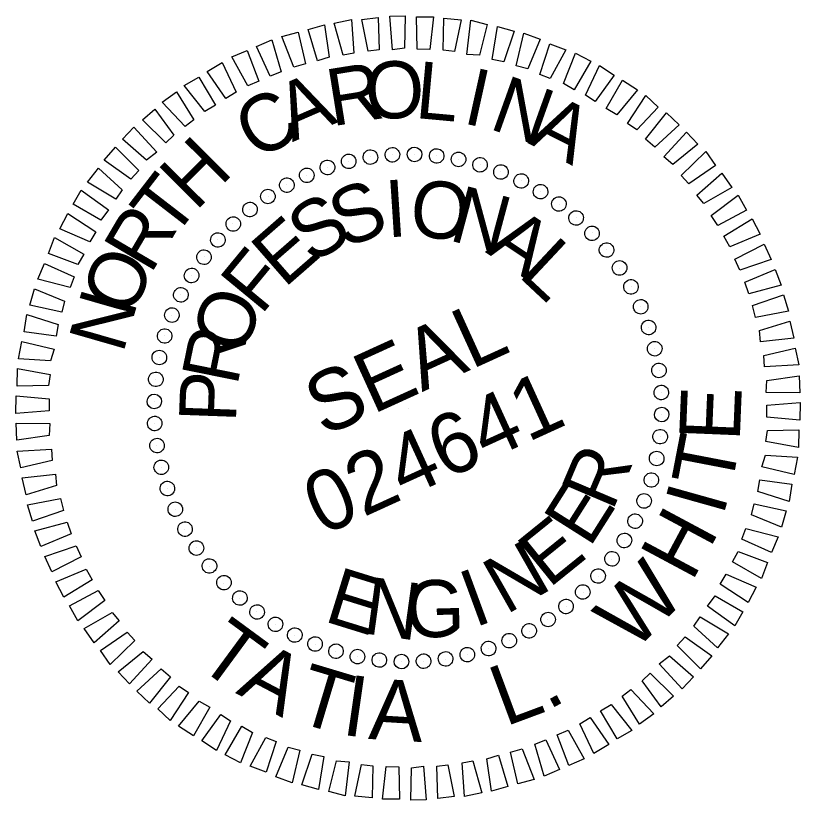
# Model space of a CAD drawing. Extents: x 2245059 to 2247045, y 661437 to 663204.
# Drawn here: x 2246812.7 to 2246890.2, y 663085.4 to 663163 of the extents above; entities that cross this region are included whole.
import ezdxf

# ---------------------------------------------------------------- set-up
doc = ezdxf.new("R2010")
doc.units = 0
doc.layers.add('Sheet Professional Seal CELL', color=7, linetype='Continuous')

msp = doc.modelspace()

# ---------------------------------------------------------------- linework, layer by layer
at = {"layer": 'Sheet Professional Seal CELL'}
for p, q in [((2246849.929, 663149.276), (2246849.929, 663149.276)), ((2246852.123, 663149.287), (2246852.123, 663149.287)), ((2246854.312, 663149.186), (2246854.312, 663149.186)), ((2246845.631, 663148.58), (2246845.631, 663148.58)), ((2246847.728, 663149.042), (2246847.728, 663149.042)), ((2246856.468, 663148.795), (2246856.468, 663148.795)), ((2246843.529, 663148.006), (2246843.529, 663148.006)), ((2246858.621, 663148.293), (2246858.621, 663148.293)), ((2246841.465, 663147.23), (2246841.465, 663147.23)), ((2246860.653, 663147.571), (2246860.653, 663147.571)), ((2246839.485, 663146.272), (2246839.485, 663146.272)), ((2246862.703, 663146.692), (2246862.703, 663146.692)), ((2246864.566, 663145.619), (2246864.566, 663145.619)), ((2246837.653, 663145.107), (2246837.653, 663145.107)), ((2246835.817, 663143.83), (2246835.817, 663143.83)), ((2246866.401, 663144.367), (2246866.401, 663144.367)), ((2246868.119, 663143.008), (2246868.119, 663143.008)), ((2246834.155, 663142.413), (2246834.155, 663142.413)), ((2246869.677, 663141.52), (2246869.677, 663141.52)), ((2246832.667, 663140.855), (2246832.667, 663140.855)), ((2246871.094, 663139.858), (2246871.094, 663139.858)), ((2246831.308, 663139.136), (2246831.308, 663139.136)), ((2246872.371, 663138.022), (2246872.371, 663138.022)), ((2246830.056, 663137.302), (2246830.056, 663137.302)), ((2246873.536, 663136.191), (2246873.536, 663136.191)), ((2246828.983, 663135.438), (2246828.983, 663135.438)), ((2246874.494, 663134.21), (2246874.494, 663134.21)), ((2246828.104, 663133.389), (2246828.104, 663133.389)), ((2246875.271, 663132.146), (2246875.271, 663132.146)), ((2246827.382, 663131.356), (2246827.382, 663131.356)), ((2246875.844, 663130.044), (2246875.844, 663130.044)), ((2246826.88, 663129.204), (2246826.88, 663129.204)), ((2246876.306, 663127.947), (2246876.306, 663127.947)), ((2246826.489, 663127.047), (2246826.489, 663127.047)), ((2246876.54, 663125.746), (2246876.54, 663125.746)), ((2246826.388, 663124.858), (2246826.388, 663124.858)), ((2246851.47, 663124.205), (2246851.47, 663124.205)), ((2246876.551, 663123.553), (2246876.551, 663123.553)), ((2246826.399, 663122.665), (2246826.399, 663122.665)), ((2246876.45, 663121.363), (2246876.45, 663121.363)), ((2246826.634, 663120.464), (2246826.634, 663120.464)), ((2246876.06, 663119.207), (2246876.06, 663119.207)), ((2246827.095, 663118.367), (2246827.095, 663118.367)), ((2246875.557, 663117.055), (2246875.557, 663117.055)), ((2246827.669, 663116.265), (2246827.669, 663116.265)), ((2246874.836, 663115.022), (2246874.836, 663115.022)), ((2246828.445, 663114.201), (2246828.445, 663114.201)), ((2246873.957, 663112.973), (2246873.957, 663112.973)), ((2246829.403, 663112.22), (2246829.403, 663112.22)), ((2246830.568, 663110.388), (2246830.568, 663110.388)), ((2246872.883, 663111.109), (2246872.883, 663111.109)), ((2246871.631, 663109.275), (2246871.631, 663109.275)), ((2246831.845, 663108.553), (2246831.845, 663108.553)), ((2246870.272, 663107.556), (2246870.272, 663107.556)), ((2246833.262, 663106.891), (2246833.262, 663106.891)), ((2246868.784, 663105.998), (2246868.784, 663105.998)), ((2246834.82, 663105.403), (2246834.82, 663105.403)), ((2246867.122, 663104.581), (2246867.122, 663104.581)), ((2246836.539, 663104.044), (2246836.539, 663104.044)), ((2246838.374, 663102.792), (2246838.374, 663102.792)), ((2246865.287, 663103.304), (2246865.287, 663103.304)), ((2246863.455, 663102.139), (2246863.455, 663102.139)), ((2246840.237, 663101.718), (2246840.237, 663101.718)), ((2246861.474, 663101.181), (2246861.474, 663101.181)), ((2246842.286, 663100.839), (2246842.286, 663100.839)), ((2246859.41, 663100.405), (2246859.41, 663100.405)), ((2246844.319, 663100.118), (2246844.319, 663100.118)), ((2246846.471, 663099.615), (2246846.471, 663099.615)), ((2246857.309, 663099.831), (2246857.309, 663099.831)), ((2246848.628, 663099.225), (2246848.628, 663099.225)), ((2246850.817, 663099.124), (2246850.817, 663099.124)), ((2246853.01, 663099.135), (2246853.01, 663099.135)), ((2246855.211, 663099.369), (2246855.211, 663099.369))]:
    msp.add_line(p, q, dxfattribs=at)
for points in [[(2246845.068, 663159.094), (2246844.175, 663162.258), (2246845.887, 663162.6), (2246846.127, 663159.302)], [(2246847.521, 663159.498), (2246846.918, 663162.63), (2246848.535, 663162.818), (2246848.622, 663159.615)], [(2246849.942, 663159.613), (2246849.681, 663162.956), (2246851.204, 663162.991), (2246851.134, 663159.771)], [(2246852.383, 663159.682), (2246852.297, 663162.885), (2246853.997, 663162.891), (2246853.612, 663159.638)], [(2246854.953, 663159.59), (2246854.999, 663162.743), (2246856.717, 663162.592), (2246856.066, 663159.438)], [(2246857.288, 663159.17), (2246857.677, 663162.535), (2246859.295, 663162.119), (2246858.537, 663159.081)], [(2246842.52, 663158.536), (2246841.601, 663161.635), (2246843.206, 663162.092), (2246843.674, 663158.898)], [(2246859.775, 663158.656), (2246860.317, 663161.926), (2246861.957, 663161.464), (2246860.93, 663158.413)], [(2246840.17, 663157.904), (2246839.004, 663160.945), (2246840.629, 663161.356), (2246841.345, 663158.22)], [(2246862.147, 663158.034), (2246862.933, 663161.25), (2246864.523, 663160.656), (2246863.322, 663157.746)], [(2246837.833, 663157.004), (2246836.485, 663159.961), (2246838.007, 663160.6), (2246838.946, 663157.456)], [(2246864.511, 663157.189), (2246865.492, 663160.219), (2246867.082, 663159.625), (2246865.525, 663156.772)], [(2246835.629, 663156.054), (2246834.053, 663158.907), (2246835.575, 663159.546), (2246836.741, 663156.506)], [(2246866.85, 663156.277), (2246868.009, 663159.278), (2246869.524, 663158.486), (2246867.902, 663155.657)], [(2246833.458, 663154.789), (2246831.63, 663157.472), (2246833.093, 663158.36), (2246834.487, 663155.423)], [(2246869.024, 663155.125), (2246870.382, 663158.052), (2246871.848, 663157.127), (2246869.964, 663154.51)], [(2246831.398, 663153.52), (2246829.343, 663156.1), (2246830.782, 663156.921), (2246832.428, 663154.154)], [(2246871.057, 663153.799), (2246872.68, 663156.627), (2246874.167, 663155.657), (2246872.109, 663153.18)], [(2246829.443, 663152.024), (2246827.181, 663154.454), (2246828.582, 663155.478), (2246830.295, 663152.687)], [(2246873.153, 663152.337), (2246874.974, 663155.091), (2246876.209, 663153.95), (2246874.093, 663151.721)], [(2246827.529, 663150.437), (2246825.238, 663152.689), (2246826.461, 663153.742), (2246828.339, 663151.191)], [(2246874.954, 663150.795), (2246877.016, 663153.384), (2246878.272, 663152.198), (2246875.866, 663150.002)], [(2246825.632, 663148.692), (2246823.246, 663150.792), (2246824.362, 663151.96), (2246826.645, 663149.484)], [(2246876.748, 663149.031), (2246878.984, 663151.479), (2246880.128, 663150.297), (2246877.639, 663148.283)], [(2246824.066, 663146.824), (2246821.448, 663148.708), (2246822.568, 663149.988), (2246824.88, 663147.69)], [(2246878.472, 663147.179), (2246880.906, 663149.553), (2246881.864, 663148.176), (2246879.226, 663146.369)], [(2246822.607, 663144.84), (2246819.804, 663146.53), (2246820.882, 663147.901), (2246823.223, 663145.781)], [(2246880.014, 663145.244), (2246882.486, 663147.415), (2246883.464, 663145.993), (2246880.722, 663144.413)], [(2246821.124, 663142.79), (2246818.383, 663144.343), (2246819.172, 663145.747), (2246821.876, 663143.793)], [(2246881.419, 663143.247), (2246884.085, 663145.232), (2246884.927, 663143.748), (2246882.099, 663142.238)], [(2246820.018, 663140.637), (2246817.066, 663141.929), (2246817.858, 663143.444), (2246820.612, 663141.623)], [(2246882.687, 663141.188), (2246885.479, 663142.9), (2246886.275, 663141.395), (2246883.276, 663140.138)], [(2246818.841, 663138.397), (2246815.927, 663139.486), (2246816.52, 663141.076), (2246819.415, 663139.428)], [(2246883.77, 663138.934), (2246886.665, 663140.419), (2246887.37, 663138.872), (2246884.268, 663137.842)], [(2246818.066, 663136.12), (2246814.895, 663136.928), (2246815.555, 663138.493), (2246818.462, 663137.18)], [(2246884.762, 663136.639), (2246887.761, 663137.896), (2246888.354, 663136.353), (2246885.169, 663135.505)], [(2246817.262, 663133.666), (2246814.087, 663134.361), (2246814.549, 663136), (2246817.525, 663134.775)], [(2246885.53, 663134.351), (2246888.566, 663135.406), (2246889.09, 663133.776), (2246885.801, 663133.156)], [(2246816.685, 663131.314), (2246813.523, 663131.741), (2246813.786, 663133.455), (2246816.883, 663132.449)], [(2246886.224, 663131.865), (2246889.211, 663132.787), (2246889.598, 663131.095), (2246886.296, 663130.744)], [(2246816.15, 663128.872), (2246812.98, 663129.076), (2246813.309, 663130.764), (2246816.505, 663130.023)], [(2246886.629, 663129.412), (2246889.719, 663130.106), (2246890.085, 663128.46), (2246886.7, 663128.29)], [(2246815.95, 663126.418), (2246812.839, 663126.373), (2246812.878, 663128.095), (2246816.102, 663127.532)], [(2246886.942, 663126.917), (2246890.136, 663127.384), (2246890.188, 663125.704), (2246886.877, 663125.733)], [(2246815.995, 663123.911), (2246812.697, 663123.671), (2246812.736, 663125.392), (2246815.993, 663125.119)], [(2246886.945, 663124.5), (2246890.242, 663124.74), (2246890.203, 663123.018), (2246886.946, 663123.292)], [(2246815.998, 663121.494), (2246812.804, 663121.027), (2246812.752, 663122.707), (2246816.062, 663122.678)], [(2246886.989, 663121.993), (2246890.101, 663122.038), (2246890.062, 663120.316), (2246886.837, 663120.879)], [(2246816.311, 663118.999), (2246813.221, 663118.304), (2246812.855, 663119.951), (2246816.239, 663120.121)], [(2246886.789, 663119.538), (2246889.959, 663119.335), (2246889.63, 663117.647), (2246886.435, 663118.388)], [(2246816.715, 663116.546), (2246813.729, 663115.624), (2246813.342, 663117.316), (2246816.644, 663117.667)], [(2246886.254, 663117.096), (2246889.416, 663116.67), (2246889.153, 663114.956), (2246886.057, 663115.962)], [(2246817.409, 663114.06), (2246814.373, 663113.005), (2246813.85, 663114.635), (2246817.139, 663115.255)], [(2246885.678, 663114.745), (2246888.852, 663114.05), (2246888.391, 663112.411), (2246885.414, 663113.636)], [(2246818.178, 663111.772), (2246815.179, 663110.515), (2246814.585, 663112.058), (2246817.771, 663112.906)], [(2246884.874, 663112.29), (2246888.044, 663111.483), (2246887.384, 663109.918), (2246884.478, 663111.231)], [(2246819.169, 663109.477), (2246816.274, 663107.992), (2246815.569, 663109.539), (2246818.671, 663110.569)], [(2246884.098, 663110.014), (2246887.013, 663108.925), (2246886.419, 663107.335), (2246883.525, 663108.983)], [(2246820.252, 663107.223), (2246817.461, 663105.511), (2246816.665, 663107.016), (2246819.663, 663108.273)], [(2246882.922, 663107.774), (2246885.874, 663106.482), (2246885.081, 663104.966), (2246882.327, 663106.788)], [(2246821.521, 663105.164), (2246818.854, 663103.178), (2246818.012, 663104.663), (2246820.841, 663106.173)], [(2246881.815, 663105.62), (2246884.557, 663104.068), (2246883.768, 663102.664), (2246881.063, 663104.618)], [(2246822.926, 663103.167), (2246820.454, 663100.995), (2246819.476, 663102.418), (2246822.217, 663103.998)], [(2246880.332, 663103.57), (2246883.136, 663101.881), (2246882.057, 663100.51), (2246879.717, 663102.63)], [(2246824.467, 663101.232), (2246822.033, 663098.858), (2246821.075, 663100.235), (2246823.713, 663102.042)], [(2246878.874, 663101.586), (2246881.491, 663099.703), (2246880.372, 663098.423), (2246878.06, 663100.721)], [(2246826.191, 663099.38), (2246823.955, 663096.932), (2246822.812, 663098.114), (2246825.301, 663100.128)], [(2246877.308, 663099.718), (2246879.694, 663097.619), (2246878.578, 663096.451), (2246876.295, 663098.927)], [(2246827.985, 663097.615), (2246825.923, 663095.027), (2246824.668, 663096.213), (2246827.074, 663098.409)], [(2246875.411, 663097.974), (2246877.702, 663095.722), (2246876.478, 663094.669), (2246874.6, 663097.22)], [(2246829.787, 663096.074), (2246827.965, 663093.32), (2246826.731, 663094.461), (2246828.847, 663096.689)], [(2246873.497, 663096.387), (2246875.759, 663093.956), (2246874.357, 663092.933), (2246872.645, 663095.724)], [(2246831.882, 663094.612), (2246830.26, 663091.783), (2246828.773, 663092.754), (2246830.831, 663095.231)], [(2246871.541, 663094.891), (2246873.597, 663092.311), (2246872.158, 663091.49), (2246870.511, 663094.256)], [(2246833.916, 663093.286), (2246832.558, 663090.359), (2246831.092, 663091.284), (2246832.976, 663093.901)], [(2246869.482, 663093.622), (2246871.31, 663090.939), (2246869.846, 663090.051), (2246868.452, 663092.988)], [(2246836.09, 663092.134), (2246834.93, 663089.132), (2246833.415, 663089.925), (2246835.038, 663092.753)], [(2246867.311, 663092.357), (2246868.887, 663089.504), (2246867.365, 663088.865), (2246866.198, 663091.905)], [(2246838.429, 663091.222), (2246837.447, 663088.192), (2246835.858, 663088.786), (2246837.414, 663091.639)], [(2246865.106, 663091.407), (2246866.455, 663088.45), (2246864.933, 663087.811), (2246863.994, 663090.955)], [(2246840.793, 663090.377), (2246840.006, 663087.16), (2246838.416, 663087.754), (2246839.617, 663090.665)], [(2246862.769, 663090.506), (2246863.936, 663087.466), (2246862.31, 663087.055), (2246861.595, 663090.19)], [(2246843.164, 663089.755), (2246842.622, 663086.485), (2246840.983, 663086.946), (2246842.01, 663089.997)], [(2246860.42, 663089.875), (2246861.338, 663086.776), (2246859.733, 663086.319), (2246859.266, 663089.513)], [(2246845.652, 663089.24), (2246845.263, 663085.876), (2246843.644, 663086.292), (2246844.402, 663089.33)], [(2246847.986, 663088.821), (2246847.94, 663085.668), (2246846.223, 663085.819), (2246846.873, 663088.973)], [(2246850.556, 663088.729), (2246850.643, 663085.526), (2246848.942, 663085.52), (2246849.327, 663088.773)], [(2246852.998, 663088.798), (2246853.258, 663085.455), (2246851.735, 663085.42), (2246851.806, 663088.639)], [(2246855.418, 663088.913), (2246856.022, 663085.781), (2246854.404, 663085.593), (2246854.318, 663088.796)], [(2246857.871, 663089.317), (2246858.765, 663086.152), (2246857.052, 663085.811), (2246856.812, 663089.109)]]:
    msp.add_lwpolyline(points, close=True, dxfattribs=at)
for centre, major_axis in [((2246849.933, 663149.238), (-0.044, 0.719)), ((2246852.121, 663149.277), (0.019, 0.72)), ((2246845.61, 663148.591), (-0.168, 0.7)), ((2246847.757, 663149.009), (-0.107, 0.712)), ((2246854.304, 663149.125), (0.081, 0.715)), ((2246856.465, 663148.783), (0.143, 0.706)), ((2246843.507, 663147.988), (-0.229, 0.683)), ((2246858.588, 663148.254), (0.204, 0.69)), ((2246841.464, 663147.203), (-0.287, 0.66)), ((2246860.657, 663147.542), (0.264, 0.67)), ((2246839.498, 663146.244), (-0.344, 0.633)), ((2246862.656, 663146.653), (0.321, 0.644)), ((2246864.569, 663145.592), (0.376, 0.614)), ((2246837.623, 663145.116), (-0.398, 0.6)), ((2246835.853, 663143.83), (-0.448, 0.563)), ((2246866.384, 663144.369), (0.428, 0.579)), ((2246868.084, 663142.993), (0.477, 0.539)), ((2246834.202, 663142.394), (-0.496, 0.522)), ((2246869.658, 663141.473), (0.522, 0.496)), ((2246832.682, 663140.82), (-0.539, 0.477)), ((2246871.094, 663139.822), (0.563, 0.448)), ((2246831.306, 663139.119), (-0.579, 0.428)), ((2246872.381, 663138.052), (0.6, 0.398)), ((2246830.083, 663137.305), (-0.614, 0.376)), ((2246873.508, 663136.177), (0.633, 0.344)), ((2246829.022, 663135.391), (-0.644, 0.321)), ((2246874.467, 663134.211), (0.66, 0.287)), ((2246828.133, 663133.392), (-0.67, 0.264)), ((2246875.252, 663132.169), (0.683, 0.229)), ((2246827.421, 663131.323), (-0.69, 0.204)), ((2246875.856, 663130.065), (0.7, 0.168)), ((2246826.892, 663129.2), (-0.706, 0.143)), ((2246876.273, 663127.918), (0.712, 0.107)), ((2246826.55, 663127.039), (-0.715, 0.081)), ((2246876.503, 663125.742), (0.719, 0.044)), ((2246826.398, 663124.857), (-0.72, 0.019)), ((2246876.541, 663123.554), (0.72, -0.019)), ((2246826.437, 663122.669), (-0.719, -0.044)), ((2246876.389, 663121.372), (0.715, -0.081)), ((2246826.666, 663120.493), (-0.712, -0.107)), ((2246876.047, 663119.211), (0.706, -0.143)), ((2246827.084, 663118.345), (-0.7, -0.168)), ((2246875.518, 663117.087), (0.69, -0.204)), ((2246827.687, 663116.242), (-0.683, -0.229)), ((2246874.807, 663115.019), (0.67, -0.264)), ((2246828.472, 663114.2), (-0.66, -0.287)), ((2246873.917, 663113.02), (0.644, -0.321)), ((2246829.432, 663112.234), (-0.633, -0.344)), ((2246872.857, 663111.106), (0.614, -0.376)), ((2246830.559, 663110.358), (-0.6, -0.398)), ((2246871.634, 663109.292), (0.579, -0.428)), ((2246831.845, 663108.589), (-0.563, -0.448)), ((2246870.257, 663107.591), (0.539, -0.477)), ((2246833.281, 663106.938), (-0.522, -0.496)), ((2246868.738, 663106.017), (0.496, -0.522)), ((2246834.855, 663105.418), (-0.477, -0.539)), ((2246867.087, 663104.581), (0.448, -0.563)), ((2246836.556, 663104.041), (-0.428, -0.579)), ((2246838.37, 663102.818), (-0.376, -0.614)), ((2246865.317, 663103.295), (0.398, -0.6)), ((2246863.442, 663102.167), (0.344, -0.633)), ((2246840.284, 663101.758), (-0.321, -0.644)), ((2246861.475, 663101.208), (0.287, -0.66)), ((2246842.283, 663100.869), (-0.264, -0.67)), ((2246859.433, 663100.423), (0.229, -0.683)), ((2246844.352, 663100.157), (-0.204, -0.69)), ((2246846.475, 663099.628), (-0.143, -0.706)), ((2246857.33, 663099.82), (0.168, -0.7)), ((2246848.636, 663099.286), (-0.081, -0.715)), ((2246850.819, 663099.134), (-0.019, -0.72)), ((2246853.006, 663099.173), (0.044, -0.719)), ((2246855.182, 663099.402), (0.107, -0.712))]:
    msp.add_ellipse(centre, major_axis=major_axis, ratio=0.999708, dxfattribs=at)

# ---------------------------------------------------------------- texts
for s, height, rotation, p in [('O', 5.638, 1.93343, (2246847.302, 663152.749)), ('R', 5.638, 9.13336, (2246843.943, 663152.041)), ('L', 5.638, 354.73314, (2246852.073, 663152.891)), ('I', 5.638, 347.5324, (2246856.754, 663152.388)), ('N', 5.639, 340.33117, (2246859.353, 663151.869)), ('A', 5.638, 23.53258, (2246840.038, 663150.481)), ('C', 5.638, 30.73213, (2246836.569, 663148.569)), ('A', 5.639, 333.12941, (2246863.261, 663150.409)), ('H', 5.638, 45.13174, (2246830.483, 663143.596)), ('T', 5.638, 52.33203, (2246828.211, 663140.746)), ('S', 5.638, 22.41266, (2246845.186, 663139.914)), ('I', 5.638, 3.70186, (2246849.389, 663141.061)), ('O', 5.638, 354.34574, (2246851.499, 663141.254)), ('N', 5.638, 344.98887, (2246855.377, 663140.824)), ('S', 5.638, 31.76787, (2246841.931, 663138.375)), ('R', 5.638, 59.53277, (2246826.03, 663137.334)), ('E', 5.638, 41.12333, (2246839.228, 663135.988)), ('A', 5.639, 326.27253, (2246859.049, 663139.641)), ('L', 5.639, 316.91311, (2246862.254, 663137.311)), ('F', 5.638, 50.47929, (2246836.939, 663133.296)), ('O', 5.638, 66.734, (2246824.177, 663133.082)), ('N', 5.639, 73.93576, (2246823.288, 663129.489)), ('O', 5.639, 69.1935, (2246835.16, 663129.243)), ('SEAL', 5.9982, 24.51226, (2246843.112, 663121.327)), ('R', 5.639, 78.55191, (2246834.584, 663126.287)), ('P', 5.639, 87.91115, (2246834.456, 663122.712)), ('024641', 5.9982, 24.51226, (2246842.99, 663111.537)), ('E', 5.998, 87.63115, (2246884.25, 663120.848)), ('T', 5.998, 79.10933, (2246883.39, 663116.027)), ('R', 5.639, 66.99367, (2246871.663, 663113.905)), ('E', 5.638, 57.63635, (2246869.408, 663110.294)), ('I', 5.998, 74.34486, (2246882.6, 663113.404)), ('H', 5.998, 61.83328, (2246879.521, 663106.917)), ('E', 5.638, 38.92402, (2246865.395, 663106.321)), ('N', 5.638, 29.56865, (2246861.14, 663103.721)), ('W', 5.998, 46.12601, (2246873.793, 663099.968)), ('E', 5.638, 342.78915, (2246843.041, 663103.162)), ('I', 5.638, 20.21346, (2246858.03, 663102.468)), ('N', 5.638, 352.14622, (2246846.891, 663101.95)), ('G', 5.638, 1.5025, (2246851.282, 663101.479)), ('T', 5.998, 323.6774, (2246830.376, 663098.89)), ('A', 5.998, 332.19922, (2246834.361, 663096.044)), ('T', 5.998, 343.27759, (2246840.091, 663093.281)), ('L', 5.998, 20.42498, (2246861.074, 663092.685)), ('I', 5.998, 351.79941, (2246844.799, 663091.936)), ('A', 5.998, 356.56388, (2246847.502, 663091.494)), ('.', 5.998, 28.28829, (2246865.296, 663094.295))]:
    msp.add_text(s, height=height, rotation=rotation, dxfattribs=at).set_placement(p)

doc.saveas('drawing.dxf')
